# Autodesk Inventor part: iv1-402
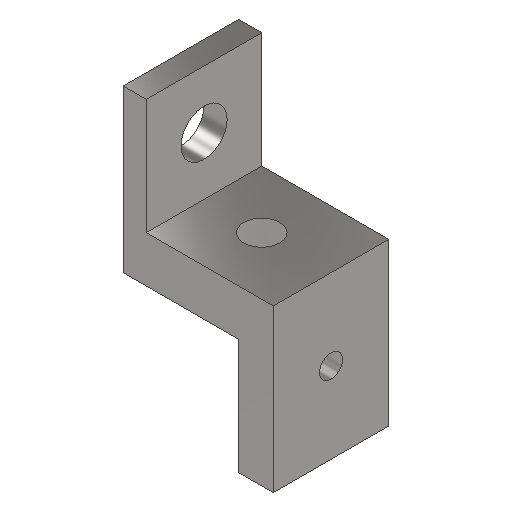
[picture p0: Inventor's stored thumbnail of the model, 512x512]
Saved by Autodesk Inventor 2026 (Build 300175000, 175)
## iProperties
Shininess: 64.0
Angle Display Precision: 2
Document Length Units: 11269
Document Angle Units: 11279
Document Time Units: 11290
Document Mass Units: 11283
Document Length Units Precision: 3
Document Angle Units Precision: 2
Created: 2002-04
Part Number: iv1-402
Document SubType Name: Modeling
Designer: Lars Bertram Pedersen
Material: Steel, Mild
Density: 7.85 g/cm^3
Appearance: Semi-Polished
Mass: 937.341 g
Surface Area: 245.107 cm^2
Volume: 119.406 cm^3
Density: 0.0
Volumn: 0.0
Area: 0.0
PropertySet Name: Model Information
Control State: 0
Master: False
Checked Out: False
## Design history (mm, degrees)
sketch "Sketch1"
  geometry: L1 (-50, 120)-(-40, 120); L2 (-40, 120)-(-40, 70); L3 (-40, 70)-(15, 70); L4 (15, 70)-(15, 0); L5 (15, 0)-(0, 0); L6 (0, 0)-(0, 50); L7 (0, 50)-(-50, 50); L8 (-50, 50)-(-50, 120); 1 further point
  constraints: 16 end point, 4 parallel, 3 perpendicular, 1 coincident, 1 horizontal
  dimensions: "d3" = 50 distance of L6.end L7.end; "d4" = 15 distance of L4.end L5.end; "d5" = 50 distance between parallel lines of L5 L7; "d8" = 50 distance of L1.end L2.end; "d9" = 10 distance of L1.start L1.end; "d10" = 20 distance between parallel lines of L7 L3
extrude "Extrusion1" new body sketch "Sketch1" distance "d11" = 50; taper "d12" = 0 deg
sketch "Sketch2"
  geometry: L1 (0, 50)-(0, 0) reference; L2 (0, 50)-(-50, 50) reference; C1 r 10 at (-25, 25)
  constraints: 1 centre point
  dimensions: "d13" = 20 diameter of C1; "d14" = 25 distance from line of L2 C1.centre; "d15" = 25 distance from line of L1 C1.centre
extrude "Extrusion2" cut sketch "Sketch2" extent not by distance; stored distance "d16" = 50; taper "d17" = 0 deg
sketch "Sketch4"
  geometry: L1 (-50, 70)-(-50, 0) reference; L2 (0, 0)-(-50, 0) reference; C1 r 5 at (-25, 35)
  constraints: 1 centre point
  dimensions: "d23" = 10 diameter of C1; "d24" = 25 distance from line of L1 C1.centre; "d25" = 35 distance from line of L2 C1.centre
extrude "Extrusion4" cut sketch "Sketch4" distance "d26" = 50; taper "d27" = 0 deg
sketch "Sketch5"
  geometry: L1 (0, 0)-(0, -50) reference; L2 (0, -50)-(55, -50) reference; C1 r 7.75 at (25, -25); 1 further point
  constraints: 1 centre point
  dimensions: "d28" = 25 distance from line of C1.centre L1; "d29" = 25 distance from line of L2 C1.centre; "d30" = 15.5 diameter of C1
extrude "Extrusion5" cut sketch "Sketch5" extent not by distance; stored distance "d31" = 0; taper "d32" = 0 deg
body "Solid1"
